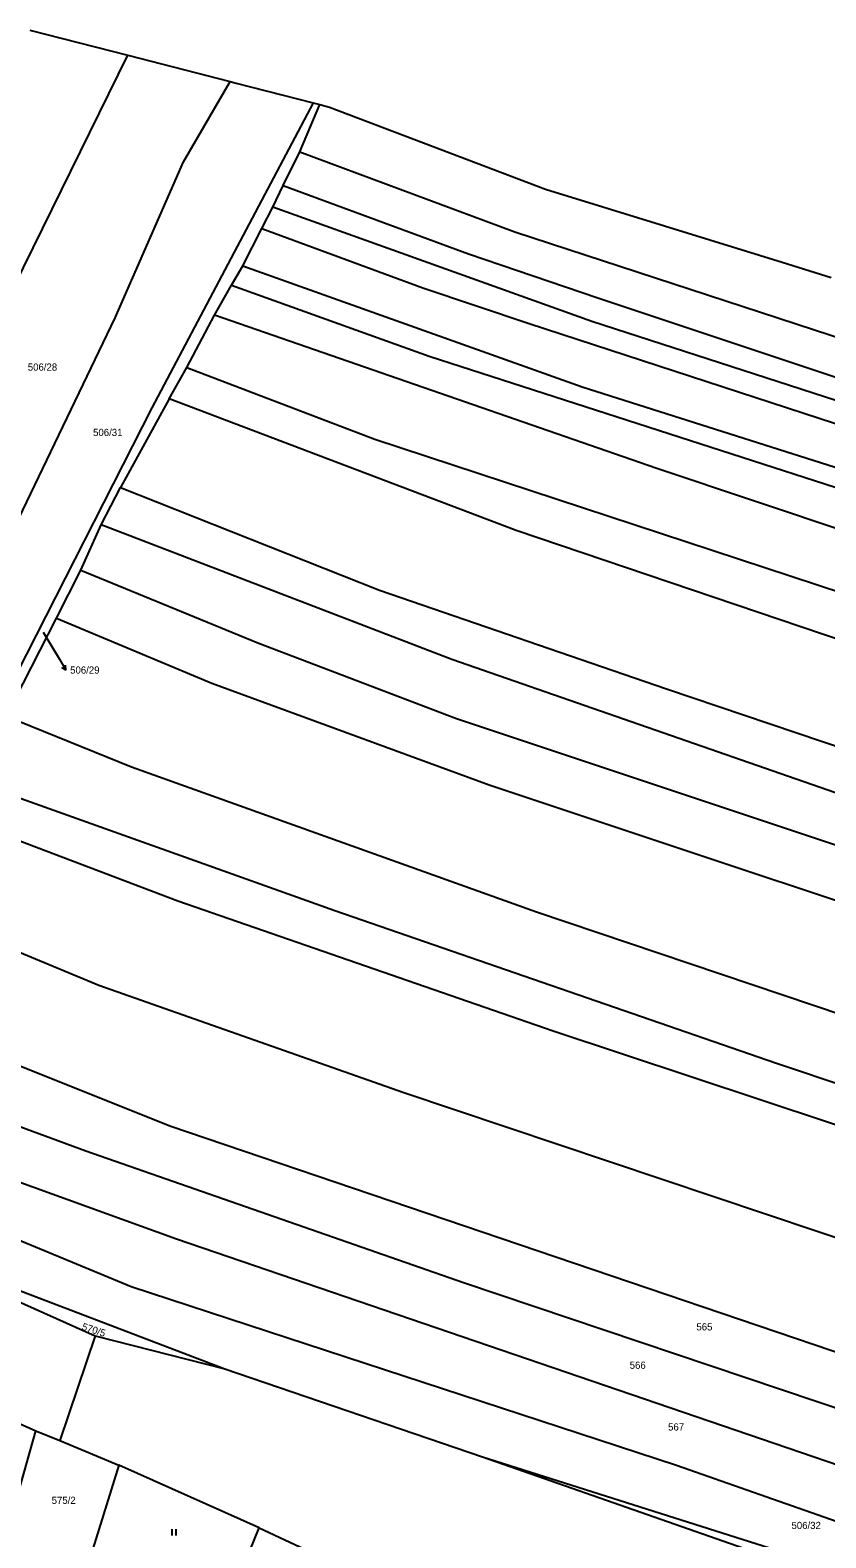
# Model space of a CAD drawing. Extents: x -744566 to -741843, y -1128407 to -1126744.
# Drawn here: x -742498.8 to -742310.3, y -1127136.3 to -1126779.2 of the extents above; entities that cross this region are included whole.
import ezdxf

# ---------------------------------------------------------------- set-up
doc = ezdxf.new("R2010")
doc.units = 0
for name, color, linetype in [('Hranice parcel', 7, 'Continuous'), ('Parcelní čísla', 7, 'Continuous'), ('Pop  PČ popisy', 7, 'Continuous'), ('Značky kultur', 7, 'Continuous')]:
    doc.layers.add(name, color=color, linetype=linetype)

msp = doc.modelspace()

# ---------------------------------------------------------------- linework, layer by layer
at = {"layer": 'Hranice parcel'}
for p, q in [((-742498.85, -1126779.22), (-742475.66, -1126785.18)), ((-742475.66, -1126785.18), (-742451.42, -1126791.4)), ((-742434.93, -1126808.05), (-742430.18, -1126796.86)), ((-742431.72, -1126796.46), (-742430.18, -1126796.86)), ((-742438.82, -1126815.98), (-742434.93, -1126808.05)), ((-742441.29, -1126821.14), (-742438.82, -1126815.98)), ((-742443.9, -1126826.23), (-742441.29, -1126821.14)), ((-742448.41, -1126835.02), (-742443.9, -1126826.23)), ((-742451.1, -1126839.6), (-742448.41, -1126835.02)), ((-742455.11, -1126846.76), (-742451.1, -1126839.6)), ((-742461.67, -1126859.1), (-742455.11, -1126846.76)), ((-742465.86, -1126866.52), (-742461.67, -1126859.1)), ((-742465.86, -1126866.52), (-742477.38, -1126887.58)), ((-742481.95, -1126896.36), (-742477.38, -1126887.58)), ((-742486.79, -1126907.12), (-742481.95, -1126896.36)), ((-742492.57, -1126918.49), (-742486.79, -1126907.12)), ((-742504.35, -1126941.71), (-742492.57, -1126918.49)), ((-742483.35, -1127088.47), (-742491.78, -1127113.29)), ((-742483.35, -1127088.47), (-742452.64, -1127096.27)), ((-742452.64, -1127096.27), (-742391.64, -1127117.14)), ((-742504.39, -1127135.7), (-742497.42, -1127110.95)), ((-742497.42, -1127110.95), (-742491.78, -1127113.29)), ((-742491.78, -1127113.29), (-742477.79, -1127119.09)), ((-742477.79, -1127119.09), (-742484.3, -1127140.22)), ((-742444.54, -1127133.92), (-742477.79, -1127119.09)), ((-742454.04, -1127157.35), (-742444.54, -1127133.92))]:
    msp.add_line(p, q, dxfattribs=at)
for points in [[(-742562.72, -1126972.14), (-742511.64, -1126858.28), (-742475.66, -1126785.18)], [(-742576.22, -1127042.62), (-742572.46, -1127037.81), (-742549.96, -1126996.44), (-742502.42, -1126896.85), (-742478.65, -1126847.35), (-742462.47, -1126810.41), (-742451.42, -1126791.4)], [(-742451.42, -1126791.4), (-742450, -1126791.77), (-742431.72, -1126796.46)], [(-742431.72, -1126796.46), (-742469.95, -1126868.69), (-742501.91, -1126931.51), (-742517.1, -1126960.81), (-742540.36, -1126998.76), (-742553.75, -1127021.53), (-742568.92, -1127039.08), (-742575.31, -1127045.24)], [(-742430.18, -1126796.86), (-742427.9, -1126797.45), (-742403.35, -1126806.76), (-742376.71, -1126816.86), (-742348.55, -1126825.56), (-742320.68, -1126834.18), (-742309.03, -1126837.78)], [(-742434.93, -1126808.05), (-742383.95, -1126826.97), (-742163.59, -1126899.11), (-742045.77, -1126940.83)], [(-742438.82, -1126815.98), (-742394.95, -1126832.23), (-742364.36, -1126842.59), (-742205.97, -1126895.42), (-742047.88, -1126947.84)], [(-742047.88, -1126947.84), (-742049.19, -1126952.47), (-742228, -1126892.81), (-742365.77, -1126848.2), (-742441.29, -1126821.14)], [(-742443.9, -1126826.23), (-742405.75, -1126840.23), (-742380.59, -1126848.67), (-742170.7, -1126917.2)], [(-742448.41, -1126835.02), (-742368.08, -1126863.73), (-742289.94, -1126888.49), (-742173.2, -1126927.29)], [(-742451.1, -1126839.6), (-742404.27, -1126856.43), (-742275.83, -1126897.91), (-742156.13, -1126938.74), (-742097.85, -1126957.39)], [(-742097.97, -1126967.72), (-742211.09, -1126929.59), (-742350.35, -1126883.06), (-742455.11, -1126846.76)], [(-742461.67, -1126859.1), (-742417.12, -1126876.07), (-742213.93, -1126942.95), (-742076.69, -1126991.19)], [(-742080.25, -1127004.92), (-742128.87, -1126986.52), (-742295.26, -1126927.65), (-742383.7, -1126897.74), (-742465.86, -1126866.52)], [(-742477.38, -1126887.58), (-742416.04, -1126911.9), (-742348.05, -1126935.25), (-742114.93, -1127013.93), (-742085.96, -1127023.63)], [(-742089.28, -1127034.5), (-742293.25, -1126965), (-742398.92, -1126928.26), (-742481.95, -1126896.36)], [(-742486.79, -1126907.12), (-742444.87, -1126924.33), (-742397.83, -1126942.23), (-742288.59, -1126978.66), (-742195.26, -1127011.61), (-742092.54, -1127045.19)], [(-742492.57, -1126918.49), (-742455.79, -1126933.86), (-742390.03, -1126957.98), (-742252.16, -1127003.9), (-742129.68, -1127044.77), (-742095.98, -1127056.46)], [(-742504.35, -1126941.71), (-742474.75, -1126953.67), (-742378.88, -1126988.04), (-742204.08, -1127046.96), (-742100.58, -1127080.82), (-742076.73, -1127089.67), (-742044, -1127103.72)], [(-742512.02, -1126957.27), (-742426.6, -1126987.75), (-742322.02, -1127023.9), (-742152.02, -1127080.85), (-742092.77, -1127100.11), (-742049.6, -1127117.15)], [(-742516.09, -1126965.6), (-742463.84, -1126985.43), (-742374.91, -1127016.27), (-742226.88, -1127065.31), (-742153.9, -1127090.43), (-742091.98, -1127111.83), (-742053.72, -1127127.51)], [(-742527.24, -1126986.86), (-742482.52, -1127005.44), (-742410.26, -1127030.86), (-742263.45, -1127080.11), (-742124.08, -1127127.86), (-742062.93, -1127150.64)], [(-742540.51, -1127007.89), (-742508.14, -1127021.79), (-742465.67, -1127038.76), (-742304.51, -1127093.48), (-742186.57, -1127134.04), (-742101.64, -1127162.49), (-742071.1, -1127173.63)], [(-742548.14, -1127019.47), (-742535.36, -1127026.31), (-742485.61, -1127044.66), (-742396.17, -1127075.85), (-742237.29, -1127129.3), (-742102.44, -1127175.98), (-742075.64, -1127186.64)], [(-742556.03, -1127030.18), (-742540.54, -1127037.88), (-742464.14, -1127065.48), (-742257.87, -1127136.04), (-742181.95, -1127162.82), (-742111.16, -1127186.39), (-742079.42, -1127198.6)], [(-742081.6, -1127209.14), (-742129.12, -1127193.01), (-742202.75, -1127169.34), (-742345.7, -1127119.16), (-742474.83, -1127076.87), (-742507.28, -1127063.47), (-742545.28, -1127047.75), (-742563.37, -1127039.11)], [(-742570.42, -1127047.48), (-742519.53, -1127070.81), (-742452.64, -1127096.27)], [(-742570.42, -1127047.48), (-742554.29, -1127056.77), (-742483.35, -1127088.47)], [(-742529.16, -1127097), (-742515.45, -1127102.99), (-742497.42, -1127110.95)], [(-742391.64, -1127117.14), (-742294.31, -1127148.02), (-742109.57, -1127211.92)], [(-742391.64, -1127117.14), (-742217.48, -1127178.02), (-742173.31, -1127193), (-742109.57, -1127211.92)], [(-742444.54, -1127133.92), (-742428.8, -1127141.29), (-742414.29, -1127147.66), (-742405.54, -1127151.64)]]:
    msp.add_lwpolyline(points, dxfattribs=at)
at = {"layer": 'Pop  PČ popisy'}
for p, q in [((-742495.71, -1126921.8), (-742491.86, -1126928.21)), ((-742491.86, -1126928.21), (-742490.314, -1126930.782)), ((-742490.314, -1126930.782), (-742491.259, -1126930.182)), ((-742490.314, -1126930.782), (-742490.401, -1126929.666))]:
    msp.add_line(p, q, dxfattribs=at)
at = {"layer": 'Značky kultur'}
for p, q in [((-742465.171, -1127135.74), (-742465.171, -1127134.24)), ((-742464.17, -1127135.74), (-742464.17, -1127134.24))]:
    msp.add_line(p, q, dxfattribs=at)

# ---------------------------------------------------------------- texts
at = {"layer": 'Parcelní čísla'}
for s, p in [('506/28', (-742499.34, -1126859.87)), ('506/31', (-742483.88, -1126875.35)), ('506/29', (-742489.31, -1126931.63)), ('565', (-742340.98, -1127087.2)), ('566', (-742356.78, -1127096.29)), ('567', (-742347.69, -1127110.91)), ('575/2', (-742493.69, -1127128.29)), ('506/32', (-742318.46, -1127134.24))]:
    msp.add_text(s, height=1.7, dxfattribs=at).set_placement(p)
msp.add_text('570/5', height=1.7, rotation=342, dxfattribs=at).set_placement((-742486.682, -1127086.998))

doc.saveas('drawing.dxf')
